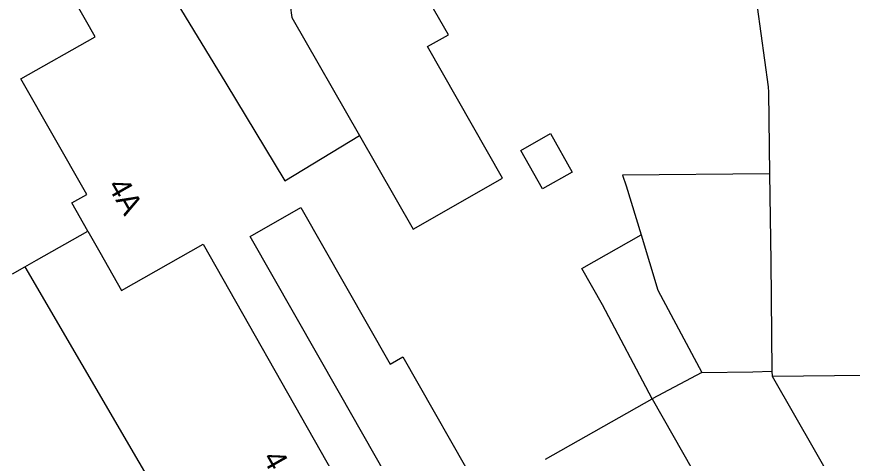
# Model space of a CAD drawing. Extents: x 159961 to 160856, y 382704 to 383353.
# Drawn here: x 160111.99 to 160150, y 383250.17 to 383270.29 of the extents above; entities that cross this region are included whole.
import ezdxf

# ---------------------------------------------------------------- set-up
doc = ezdxf.new("R2010")
doc.units = 0
for name, color, linetype in [('IMGEO_Pand', 7, 'Continuous'), ('IMGEO_Pand_nummerreeks', 7, 'Continuous'), ('IMGEO_Voetpad_open', 7, 'Continuous')]:
    doc.layers.add(name, color=color, linetype=linetype)

msp = doc.modelspace()

# ---------------------------------------------------------------- linework, layer by layer
at = {"layer": 'IMGEO_Pand'}
for points in [[(160146.349, 383253.911), (160153.457, 383253.993), (160153.79, 383253.997), (160153.481, 383276.747), (160153.377, 383284.295)], [(160115.222, 383260.517), (160114.489, 383261.809), (160115.168, 383262.194), (160112.178, 383267.468), (160115.547, 383269.378), (160112.287, 383275.129), (160112.578, 383275.132), (160112.533, 383279.05), (160112.497, 383283.646), (160112.496, 383283.812)], [(160123.651, 383283.915), (160123.746, 383275.732), (160124.508, 383270.257), (160127.588, 383264.881)], [(160127.588, 383264.881), (160130.029, 383260.62), (160134.089, 383262.933), (160130.674, 383268.928), (160131.626, 383269.47), (160130.551, 383271.356), (160130.5, 383275.79)], [(160118.234, 383275.685), (160119.098, 383271.217), (160121.495, 383267.263), (160124.187, 383262.82), (160127.588, 383264.881)], [(160145.673, 383270.75), (160146.176, 383267.1), (160146.182, 383266.849), (160146.233, 383263.133)], [(160136.264, 383264.966), (160137.258, 383263.209), (160135.908, 383262.445), (160134.914, 383264.202), (160136.264, 383264.966)], [(160146.233, 383263.133), (160139.539, 383263.067), (160139.712, 383262.582), (160140.391, 383260.352)], [(160146.233, 383263.133), (160146.288, 383259.139), (160146.346, 383254.139)], [(160135.659, 383237.322), (160126.665, 383253.145), (160122.607, 383260.283), (160124.913, 383261.594), (160128.971, 383254.455), (160129.558, 383254.789), (160133.145, 383248.48)], [(160112.35, 383258.891), (160112.892, 383259.198), (160115.222, 383260.517)], [(160115.222, 383260.517), (160115.762, 383259.564), (160116.752, 383257.817), (160120.475, 383259.928), (160126.102, 383250), (160129.198, 383244.593), (160131.506, 383240.532), (160133.977, 383236.185)], [(160140.9, 383252.888), (160138.634, 383257.173), (160137.697, 383258.821), (160140.391, 383260.352)], [(160140.391, 383260.352), (160141.158, 383257.837), (160143.151, 383254.083)], [(160111.792, 383258.574), (160112.35, 383258.891)], [(160112.35, 383258.891), (160117.54, 383250), (160120.35, 383245.187), (160128.149, 383231.828)], [(160143.151, 383254.083), (160140.9, 383252.888)], [(160143.151, 383254.083), (160145.473, 383254.11), (160146.346, 383254.139)], [(160146.346, 383254.139), (160146.349, 383253.911)], [(160136.049, 383250.131), (160140.9, 383252.888)], [(160140.9, 383252.888), (160143.222, 383248.803)]]:
    msp.add_lwpolyline(points, dxfattribs=at)
at = {"layer": 'IMGEO_Voetpad_open'}
msp.add_lwpolyline([(160146.349, 383253.911), (160149.29, 383248.802), (160149.722, 383248.052), (160147.755, 383244.967), (160145.738, 383244.377)], dxfattribs=at)

# ---------------------------------------------------------------- texts
at = {"layer": 'IMGEO_Pand_nummerreeks'}
msp.add_text('4A                                  4', height=1, rotation=299.6102, dxfattribs=at).set_placement((160116.093, 383262.593))

doc.saveas('drawing.dxf')
